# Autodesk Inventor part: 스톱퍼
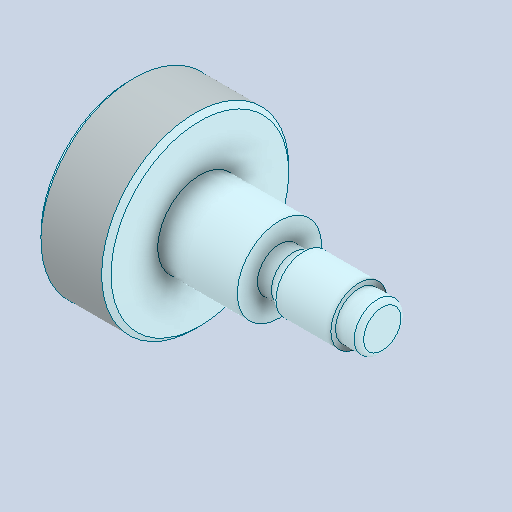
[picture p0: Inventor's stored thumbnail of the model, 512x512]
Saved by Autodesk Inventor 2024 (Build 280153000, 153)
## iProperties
Created: 2024-07
Part Number: 스톱퍼
Material: 강철, 탄소
Document SubType Name: Modeling
Designer: com
Density: 7.85 g/cm^3
Appearance: 기본값
Author: jhkim
Sending System: Autodesk Inventor 2025
Preprocessor: ST-DEVELOPER v20
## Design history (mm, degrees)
feature "솔리드1"
node "솔리드2"
